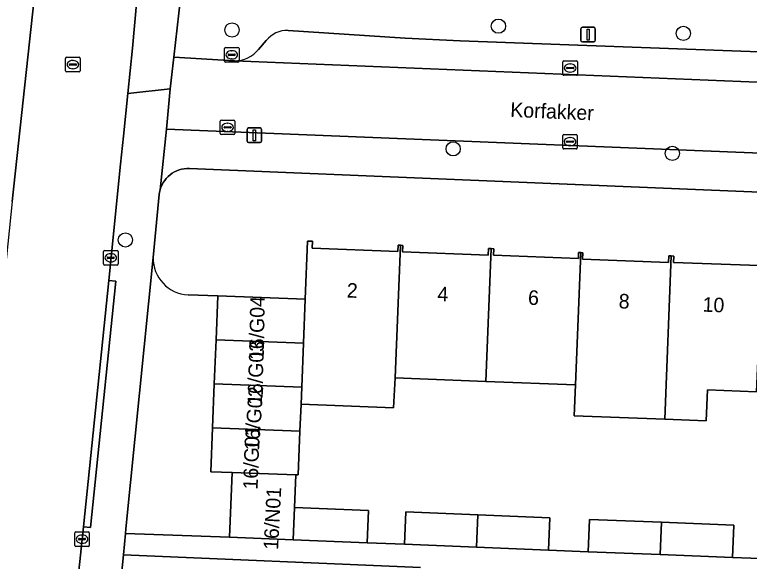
# Model space of a CAD drawing. Extents: x 161354 to 162026, y 386504 to 387460.
# Drawn here: x 161810.3 to 161860.6, y 386901.3 to 386938.8 of the extents above; entities that cross this region are included whole.
import ezdxf

# ---------------------------------------------------------------- set-up
doc = ezdxf.new("R2010")
doc.units = 0
for name, color, linetype in [('IMGEO_Boom', 7, 'Continuous'), ('IMGEO_Erf', 7, 'Continuous'), ('IMGEO_Kolk', 7, 'Continuous'), ('IMGEO_Lichtmast', 7, 'Continuous'), ('IMGEO_Openbare_ruimte_label', 7, 'Continuous'), ('IMGEO_Pand', 7, 'Continuous'), ('IMGEO_Pand_nummerreeks', 7, 'Continuous'), ('IMGEO_Parkeervlak_open', 7, 'Continuous'), ('IMGEO_Rijbaan_lokaal_open', 7, 'Continuous'), ('IMGEO_Rioolput', 7, 'Continuous'), ('IMGEO_Voetpad_gesloten', 7, 'Continuous'), ('IMGEO_Voetpad_open', 7, 'Continuous')]:
    doc.layers.add(name, color=color, linetype=linetype)

msp = doc.modelspace()

# ---------------------------------------------------------------- linework, layer by layer
at = {"layer": 'IMGEO_Boom'}
for centre in [(161843.429, 386938.023), (161825.164, 386937.758), (161856.108, 386937.525), (161840.325, 386929.613), (161855.353, 386929.297), (161817.853, 386923.364)]:
    msp.add_circle(centre, 0.489, dxfattribs=at)
at = {"layer": 'IMGEO_Erf'}
for points in [[(161883.379, 386925.736), (161822.24, 386928.262), (161822.062, 386928.261), (161821.885, 386928.245), (161821.709, 386928.212), (161821.538, 386928.164), (161821.371, 386928.101), (161821.211, 386928.024), (161821.058, 386927.932), (161820.915, 386927.827), (161820.781, 386927.71), (161820.658, 386927.581), (161820.547, 386927.442), (161820.449, 386927.293), (161820.364, 386927.136), (161820.294, 386926.973), (161820.239, 386926.803), (161820.199, 386926.63), (161820.177, 386926.471), (161819.756, 386922.16)], [(161822.159, 386919.611), (161824.182, 386919.533), (161830.18, 386919.302), (161830.335, 386923.288), (161830.673, 386923.275), (161830.655, 386922.794), (161836.533, 386922.568), (161836.549, 386923.007), (161836.715, 386923), (161836.879, 386922.994), (161836.862, 386922.547), (161842.727, 386922.321), (161842.745, 386922.776), (161842.928, 386922.768), (161843.11, 386922.761), (161843.093, 386922.315), (161848.91, 386922.091), (161848.926, 386922.503), (161849.07, 386922.498), (161849.216, 386922.492), (161849.2, 386922.055), (161855.091, 386921.828), (161855.108, 386922.273), (161855.28, 386922.266), (161855.452, 386922.259), (161855.436, 386921.828), (161861.312, 386921.602)], [(161861.132, 386912.953), (161857.774, 386913.082), (161857.682, 386910.965), (161854.828, 386911.075), (161848.617, 386911.314), (161848.703, 386913.432), (161842.56, 386913.668), (161836.347, 386913.907), (161836.227, 386911.855), (161829.9, 386912.098), (161829.821, 386910.252), (161829.694, 386907.265), (161829.54, 386907.27), (161829.449, 386905.022), (161834.521, 386904.817), (161834.432, 386902.599), (161836.982, 386902.496), (161837.071, 386904.714), (161842.017, 386904.515), (161846.963, 386904.316), (161846.873, 386902.097), (161849.583, 386901.988), (161849.673, 386904.206), (161854.619, 386904.007), (161859.56, 386903.808), (161859.47, 386901.589), (161861.984, 386901.488)], [(161838.091, 386900.916), (161817.712, 386901.768), (161815.368, 386878.287)]]:
    msp.add_lwpolyline(points, dxfattribs=at)
msp.add_arc((161822.254, 386922.108), 2.499, 178.8094, 267.813, dxfattribs=at)
at = {"layer": 'IMGEO_Kolk'}
for p, q in [((161824.646, 386935.632), (161824.646, 386936.484)), ((161824.721, 386936.558), (161825.573, 386936.558)), ((161825.134, 386936.338), (161825.159, 386936.338)), ((161825.647, 386936.484), (161825.647, 386935.632)), ((161824.905, 386936.052), (161824.905, 386936.064)), ((161825.343, 386936.015), (161824.945, 386936.015)), ((161824.948, 386936.101), (161825.346, 386936.101)), ((161825.389, 386936.064), (161825.389, 386936.052)), ((161825.573, 386935.558), (161824.721, 386935.558)), ((161825.157, 386935.778), (161825.132, 386935.778)), ((161847.846, 386934.726), (161847.846, 386935.578)), ((161847.921, 386935.652), (161848.773, 386935.652)), ((161848.334, 386935.432), (161848.359, 386935.432)), ((161848.847, 386935.578), (161848.847, 386934.726)), ((161848.105, 386935.146), (161848.105, 386935.158)), ((161848.543, 386935.109), (161848.145, 386935.109)), ((161848.148, 386935.195), (161848.546, 386935.195)), ((161848.357, 386934.872), (161848.332, 386934.872)), ((161848.589, 386935.158), (161848.589, 386935.146)), ((161848.773, 386934.652), (161847.921, 386934.652)), ((161824.356, 386930.66), (161824.356, 386931.512)), ((161824.431, 386931.586), (161825.283, 386931.586)), ((161824.844, 386931.366), (161824.869, 386931.366)), ((161825.357, 386931.512), (161825.357, 386930.66)), ((161824.615, 386931.08), (161824.615, 386931.092)), ((161825.053, 386931.043), (161824.655, 386931.043)), ((161824.658, 386931.129), (161825.056, 386931.129)), ((161824.867, 386930.806), (161824.842, 386930.806)), ((161825.099, 386931.092), (161825.099, 386931.08)), ((161825.283, 386930.586), (161824.431, 386930.586)), ((161847.836, 386929.675), (161847.836, 386930.527)), ((161847.911, 386930.601), (161848.763, 386930.601)), ((161848.324, 386930.381), (161848.349, 386930.381)), ((161848.837, 386930.527), (161848.837, 386929.675)), ((161848.095, 386930.095), (161848.095, 386930.107)), ((161848.533, 386930.058), (161848.135, 386930.058)), ((161848.138, 386930.144), (161848.536, 386930.144)), ((161848.347, 386929.821), (161848.322, 386929.821)), ((161848.579, 386930.107), (161848.579, 386930.095)), ((161848.763, 386929.601), (161847.911, 386929.601)), ((161816.351, 386921.716), (161816.351, 386922.568)), ((161816.426, 386922.642), (161817.278, 386922.642)), ((161816.839, 386922.422), (161816.864, 386922.422)), ((161817.352, 386922.568), (161817.352, 386921.716)), ((161816.61, 386922.136), (161816.61, 386922.148)), ((161817.048, 386922.099), (161816.65, 386922.099)), ((161816.653, 386922.185), (161817.051, 386922.185)), ((161816.862, 386921.862), (161816.837, 386921.862)), ((161817.094, 386922.148), (161817.094, 386922.136)), ((161817.278, 386921.642), (161816.426, 386921.642)), ((161814.379, 386902.423), (161814.379, 386903.275)), ((161814.454, 386903.349), (161815.306, 386903.349)), ((161814.867, 386903.129), (161814.892, 386903.129)), ((161815.38, 386903.275), (161815.38, 386902.423)), ((161814.638, 386902.843), (161814.638, 386902.855)), ((161815.076, 386902.806), (161814.678, 386902.806)), ((161814.681, 386902.892), (161815.079, 386902.892)), ((161815.122, 386902.855), (161815.122, 386902.843)), ((161815.306, 386902.349), (161814.454, 386902.349)), ((161814.89, 386902.569), (161814.865, 386902.569))]:
    msp.add_line(p, q, dxfattribs=at)
for points in [[(161824.646, 386935.632), (161824.646, 386936.484)], [(161824.721, 386936.558), (161825.573, 386936.558)], [(161825.647, 386936.484), (161825.647, 386935.632)], [(161825.573, 386935.558), (161824.721, 386935.558)], [(161847.846, 386934.726), (161847.846, 386935.578)], [(161847.921, 386935.652), (161848.773, 386935.652)], [(161848.847, 386935.578), (161848.847, 386934.726)], [(161848.773, 386934.652), (161847.921, 386934.652)], [(161824.356, 386930.66), (161824.356, 386931.512)], [(161824.431, 386931.586), (161825.283, 386931.586)], [(161825.357, 386931.512), (161825.357, 386930.66)], [(161825.283, 386930.586), (161824.431, 386930.586)], [(161847.836, 386929.675), (161847.836, 386930.527)], [(161847.911, 386930.601), (161848.763, 386930.601)], [(161848.837, 386930.527), (161848.837, 386929.675)], [(161848.763, 386929.601), (161847.911, 386929.601)], [(161816.351, 386921.716), (161816.351, 386922.568)], [(161816.426, 386922.642), (161817.278, 386922.642)], [(161817.352, 386922.568), (161817.352, 386921.716)], [(161817.278, 386921.642), (161816.426, 386921.642)], [(161814.379, 386902.423), (161814.379, 386903.275)], [(161814.454, 386903.349), (161815.306, 386903.349)], [(161815.38, 386903.275), (161815.38, 386902.423)], [(161815.306, 386902.349), (161814.454, 386902.349)]]:
    msp.add_lwpolyline(points, dxfattribs=at)
for centre, radius, start, end in [((161824.723, 386936.482), 0.0765, 91.552, 178.448), ((161824.723, 386936.482), 0.0765, 91.552, 178.448), ((161825.571, 386936.482), 0.0765, 1.552, 88.448), ((161825.571, 386936.482), 0.0765, 1.552, 88.448), ((161824.945, 386936.061), 0.0403, 85.8775, 175.7526), ((161824.942, 386936.051), 0.0366, 178.938, 274.7102), ((161825.346, 386936.058), 0.043, 264.8664, 352.4533), ((161825.35, 386936.063), 0.0386, 1.7309, 96.639), ((161824.723, 386935.634), 0.0765, 181.552, 268.448), ((161824.723, 386935.634), 0.0765, 181.552, 268.448), ((161825.571, 386935.634), 0.0765, 271.552, 358.448), ((161825.571, 386935.634), 0.0765, 271.552, 358.448), ((161847.923, 386935.576), 0.0765, 91.552, 178.448), ((161847.923, 386935.576), 0.0765, 91.552, 178.448), ((161848.771, 386935.576), 0.0765, 1.552, 88.448), ((161848.771, 386935.576), 0.0765, 1.552, 88.448), ((161848.145, 386935.155), 0.0403, 85.8775, 175.7526), ((161848.142, 386935.145), 0.0366, 178.938, 274.7102), ((161848.546, 386935.152), 0.043, 264.8664, 352.4533), ((161848.55, 386935.157), 0.0386, 1.7309, 96.639), ((161847.923, 386934.728), 0.0765, 181.552, 268.448), ((161847.923, 386934.728), 0.0765, 181.552, 268.448), ((161848.771, 386934.728), 0.0765, 271.552, 358.448), ((161848.771, 386934.728), 0.0765, 271.552, 358.448), ((161824.433, 386931.51), 0.0765, 91.552, 178.448), ((161824.433, 386931.51), 0.0765, 91.552, 178.448), ((161825.281, 386931.51), 0.0765, 1.552, 88.448), ((161825.281, 386931.51), 0.0765, 1.552, 88.448), ((161824.655, 386931.089), 0.0403, 85.8775, 175.7526), ((161824.652, 386931.079), 0.0366, 178.938, 274.7102), ((161825.056, 386931.086), 0.043, 264.8664, 352.4533), ((161825.06, 386931.091), 0.0386, 1.7309, 96.639), ((161824.433, 386930.662), 0.0765, 181.552, 268.448), ((161824.433, 386930.662), 0.0765, 181.552, 268.448), ((161825.281, 386930.662), 0.0765, 271.552, 358.448), ((161825.281, 386930.662), 0.0765, 271.552, 358.448), ((161847.913, 386930.525), 0.0765, 91.552, 178.448), ((161847.913, 386930.525), 0.0765, 91.552, 178.448), ((161848.761, 386930.525), 0.0765, 1.552, 88.448), ((161848.761, 386930.525), 0.0765, 1.552, 88.448), ((161848.135, 386930.104), 0.0403, 85.8775, 175.7526), ((161848.132, 386930.094), 0.0366, 178.938, 274.7102), ((161848.536, 386930.101), 0.043, 264.8664, 352.4533), ((161848.54, 386930.106), 0.0386, 1.7309, 96.639), ((161847.913, 386929.677), 0.0765, 181.552, 268.448), ((161847.913, 386929.677), 0.0765, 181.552, 268.448), ((161848.761, 386929.677), 0.0765, 271.552, 358.448), ((161848.761, 386929.677), 0.0765, 271.552, 358.448), ((161816.428, 386922.566), 0.0765, 91.552, 178.448), ((161816.428, 386922.566), 0.0765, 91.552, 178.448), ((161817.276, 386922.566), 0.0765, 1.552, 88.448), ((161817.276, 386922.566), 0.0765, 1.552, 88.448), ((161816.65, 386922.145), 0.0403, 85.8775, 175.7526), ((161816.647, 386922.135), 0.0366, 178.938, 274.7102), ((161817.051, 386922.142), 0.043, 264.8664, 352.4533), ((161817.055, 386922.147), 0.0386, 1.7309, 96.639), ((161816.428, 386921.718), 0.0765, 181.552, 268.448), ((161816.428, 386921.718), 0.0765, 181.552, 268.448), ((161817.276, 386921.718), 0.0765, 271.552, 358.448), ((161817.276, 386921.718), 0.0765, 271.552, 358.448), ((161814.456, 386903.273), 0.0765, 91.552, 178.448), ((161814.456, 386903.273), 0.0765, 91.552, 178.448), ((161815.304, 386903.273), 0.0765, 1.552, 88.448), ((161815.304, 386903.273), 0.0765, 1.552, 88.448), ((161814.678, 386902.852), 0.0403, 85.8775, 175.7526), ((161814.675, 386902.842), 0.0366, 178.938, 274.7102), ((161815.079, 386902.849), 0.043, 264.8664, 352.4533), ((161815.083, 386902.854), 0.0386, 1.7309, 96.639), ((161814.456, 386902.425), 0.0765, 181.552, 268.448), ((161814.456, 386902.425), 0.0765, 181.552, 268.448), ((161815.304, 386902.425), 0.0765, 271.552, 358.448), ((161815.304, 386902.425), 0.0765, 271.552, 358.448)]:
    msp.add_arc(centre, radius, start, end, dxfattribs=at)
for centre, major_axis, ratio, start_param, end_param in [((161825.133, 386936.058), (-0.387, 0.002), 0.722429, 4.712389, 7.853982), ((161825.158, 386936.058), (-0.39, 0.002), 0.717154, 1.570796, 4.712389), ((161848.333, 386935.152), (-0.387, 0.002), 0.722429, 4.712389, 7.853982), ((161848.358, 386935.152), (-0.39, 0.002), 0.717154, 1.570796, 4.712389), ((161824.843, 386931.086), (-0.387, 0.002), 0.722429, 4.712389, 7.853982), ((161824.868, 386931.086), (-0.39, 0.002), 0.717154, 1.570796, 4.712389), ((161848.323, 386930.101), (-0.387, 0.002), 0.722429, 4.712389, 7.853982), ((161848.348, 386930.101), (-0.39, 0.002), 0.717154, 1.570796, 4.712389), ((161816.838, 386922.142), (-0.387, 0.002), 0.722429, 4.712389, 7.853982), ((161816.863, 386922.142), (-0.39, 0.002), 0.717154, 1.570796, 4.712389), ((161814.866, 386902.849), (-0.387, 0.002), 0.722429, 4.712389, 7.853982), ((161814.891, 386902.849), (-0.39, 0.002), 0.717154, 1.570796, 4.712389)]:
    msp.add_ellipse(centre, major_axis=major_axis, ratio=ratio, start_param=start_param, end_param=end_param, dxfattribs=at)
at = {"layer": 'IMGEO_Lichtmast'}
for p, q in [((161849.082, 386937.047), (161849.082, 386937.847)), ((161849.082, 386937.847), (161849.082, 386937.047)), ((161849.182, 386937.947), (161849.972, 386937.947)), ((161849.972, 386937.947), (161849.182, 386937.947)), ((161850.072, 386937.847), (161850.072, 386937.047)), ((161850.072, 386937.047), (161850.072, 386937.847)), ((161849.972, 386936.947), (161849.182, 386936.947)), ((161849.182, 386936.947), (161849.972, 386936.947)), ((161826.2, 386930.142), (161826.2, 386930.942)), ((161826.2, 386930.942), (161826.2, 386930.142)), ((161826.3, 386931.042), (161827.09, 386931.042)), ((161827.09, 386931.042), (161826.3, 386931.042)), ((161827.19, 386930.942), (161827.19, 386930.142)), ((161827.19, 386930.142), (161827.19, 386930.942)), ((161827.09, 386930.042), (161826.3, 386930.042)), ((161826.3, 386930.042), (161827.09, 386930.042))]:
    msp.add_line(p, q, dxfattribs=at)
for points in [[(161849.502, 386937.822), (161849.652, 386937.822), (161849.652, 386937.072), (161849.502, 386937.072), (161849.502, 386937.822)], [(161826.62, 386930.917), (161826.77, 386930.917), (161826.77, 386930.167), (161826.62, 386930.167), (161826.62, 386930.917)]]:
    msp.add_lwpolyline(points, dxfattribs=at)
for centre, start, end in [((161849.182, 386937.847), 90, 180), ((161849.182, 386937.847), 90, 180), ((161849.972, 386937.847), 0, 90), ((161849.972, 386937.847), 360, 90), ((161849.182, 386937.047), 180, 270), ((161849.182, 386937.047), 180, 270), ((161849.972, 386937.047), 270, 0), ((161849.972, 386937.047), 270, 0), ((161826.3, 386930.942), 90, 180), ((161826.3, 386930.942), 90, 180), ((161827.09, 386930.942), 0, 90), ((161827.09, 386930.942), 360, 90), ((161826.3, 386930.142), 180, 270), ((161826.3, 386930.142), 180, 270), ((161827.09, 386930.142), 270, 0), ((161827.09, 386930.142), 270, 0)]:
    msp.add_arc(centre, 0.1, start, end, dxfattribs=at)
at = {"layer": 'IMGEO_Pand'}
for points in [[(161836.227, 386911.855), (161836.347, 386913.907), (161836.715, 386923), (161836.549, 386923.007), (161836.533, 386922.568), (161830.655, 386922.794), (161830.673, 386923.275), (161830.335, 386923.288), (161830.18, 386919.302), (161830.063, 386916.285), (161829.945, 386913.268), (161829.9, 386912.098)], [(161842.56, 386913.668), (161842.928, 386922.768), (161842.745, 386922.776), (161842.727, 386922.321), (161836.862, 386922.547), (161836.879, 386922.994), (161836.715, 386923), (161836.347, 386913.907)], [(161848.703, 386913.432), (161849.07, 386922.498), (161848.926, 386922.503), (161848.91, 386922.091), (161843.093, 386922.315), (161843.11, 386922.761), (161842.928, 386922.768), (161842.56, 386913.668)], [(161848.617, 386911.314), (161854.828, 386911.075), (161855.28, 386922.266), (161855.108, 386922.273), (161855.091, 386921.828), (161849.2, 386922.055), (161849.216, 386922.492), (161849.07, 386922.498), (161848.703, 386913.432)], [(161857.682, 386910.965), (161857.774, 386913.082), (161861.132, 386912.953), (161861.5, 386922.048), (161861.329, 386922.055), (161861.312, 386921.602), (161855.436, 386921.828), (161855.452, 386922.259), (161855.28, 386922.266), (161854.828, 386911.075)], [(161824.066, 386916.516), (161830.063, 386916.285), (161830.18, 386919.302), (161824.182, 386919.533)], [(161824.066, 386916.516), (161823.95, 386913.499), (161829.945, 386913.268), (161830.063, 386916.285)], [(161823.95, 386913.499), (161823.834, 386910.482), (161829.821, 386910.252), (161829.9, 386912.098), (161829.945, 386913.268)], [(161829.821, 386910.252), (161823.834, 386910.482), (161823.718, 386907.465), (161825.17, 386907.416), (161829.54, 386907.27), (161829.694, 386907.265)], [(161829.54, 386907.27), (161825.17, 386907.416), (161824.991, 386902.98), (161829.36, 386902.803), (161829.449, 386905.022)], [(161829.449, 386905.022), (161829.36, 386902.803), (161834.432, 386902.599), (161834.521, 386904.817)], [(161842.017, 386904.515), (161837.071, 386904.714), (161836.982, 386902.496), (161841.928, 386902.297)], [(161842.017, 386904.515), (161841.928, 386902.297), (161846.873, 386902.097), (161846.963, 386904.316)], [(161854.619, 386904.007), (161849.673, 386904.206), (161849.583, 386901.988), (161854.529, 386901.789)], [(161854.619, 386904.007), (161854.529, 386901.789), (161859.47, 386901.589), (161859.56, 386903.808)]]:
    msp.add_lwpolyline(points, close=True, dxfattribs=at)
at = {"layer": 'IMGEO_Parkeervlak_open'}
for points in [[(161840.813, 386937.012), (161837.043, 386937.189), (161829.008, 386937.73)], [(161827.515, 386937.033), (161826.99, 386936.43)], [(161865.649, 386936.106), (161840.813, 386937.012)], [(161825.331, 386935.656), (161869.016, 386933.873)]]:
    msp.add_lwpolyline(points, dxfattribs=at)
for centre, radius, start, end in [((161828.94, 386935.929), 1.802, 87.8264, 142.2242), ((161825.369, 386937.739), 2.083, 268.9502, 321.0723)]:
    msp.add_arc(centre, radius, start, end, dxfattribs=at)
at = {"layer": 'IMGEO_Rijbaan_lokaal_open'}
msp.add_lwpolyline([(161816.71, 386920.59), (161817.528, 386928.566), (161817.724, 386930.482), (161818.023, 386933.401), (161818.343, 386936.515), (161819.44, 386948.763), (161812.576, 386949.497), (161812.049, 386944.655), (161812.024, 386943.912), (161810.085, 386925.992), (161809.785, 386923.091), (161808.152, 386907.304), (161805.29, 386878.733), (161812.271, 386878.019), (161814.977, 386903.685)], close=True, dxfattribs=at)
for points in [[(161810.085, 386925.992), (161812.024, 386943.912), (161812.049, 386944.655)], [(161872.055, 386933.83), (161869.016, 386933.873), (161825.331, 386935.656), (161821.164, 386935.889), (161820.927, 386933.732), (161820.663, 386930.949), (161873.861, 386928.802)]]:
    msp.add_lwpolyline(points, dxfattribs=at)
at = {"layer": 'IMGEO_Rioolput'}
for p, q in [((161813.826, 386935.887), (161814.678, 386935.887)), ((161813.751, 386934.961), (161813.751, 386935.813)), ((161814.01, 386935.381), (161814.01, 386935.393)), ((161814.448, 386935.344), (161814.05, 386935.344)), ((161814.053, 386935.43), (161814.451, 386935.43)), ((161814.239, 386935.667), (161814.264, 386935.667)), ((161814.494, 386935.393), (161814.494, 386935.381)), ((161814.752, 386935.813), (161814.752, 386934.961)), ((161814.678, 386934.887), (161813.826, 386934.887)), ((161814.262, 386935.107), (161814.237, 386935.107))]:
    msp.add_line(p, q, dxfattribs=at)
for points in [[(161813.826, 386935.887), (161814.678, 386935.887)], [(161813.751, 386934.961), (161813.751, 386935.813)], [(161814.752, 386935.813), (161814.752, 386934.961)], [(161814.678, 386934.887), (161813.826, 386934.887)]]:
    msp.add_lwpolyline(points, dxfattribs=at)
for centre, radius, start, end in [((161813.828, 386935.811), 0.0765, 91.552, 178.448), ((161813.828, 386935.811), 0.0765, 91.552, 178.448), ((161814.676, 386935.811), 0.0765, 1.552, 88.448), ((161814.676, 386935.811), 0.0765, 1.552, 88.448), ((161814.05, 386935.39), 0.0403, 85.8775, 175.7526), ((161814.047, 386935.38), 0.0366, 178.938, 274.7102), ((161814.451, 386935.387), 0.043, 264.8664, 352.4533), ((161814.455, 386935.392), 0.0386, 1.7309, 96.639), ((161813.828, 386934.963), 0.0765, 181.552, 268.448), ((161813.828, 386934.963), 0.0765, 181.552, 268.448), ((161814.676, 386934.963), 0.0765, 271.552, 358.448), ((161814.676, 386934.963), 0.0765, 271.552, 358.448)]:
    msp.add_arc(centre, radius, start, end, dxfattribs=at)
for centre, major_axis, ratio, start_param, end_param in [((161814.238, 386935.387), (-0.387, 0.002), 0.722429, 4.712389, 7.853982), ((161814.263, 386935.387), (-0.39, 0.002), 0.717154, 1.570796, 4.712389)]:
    msp.add_ellipse(centre, major_axis=major_axis, ratio=ratio, start_param=start_param, end_param=end_param, dxfattribs=at)
at = {"layer": 'IMGEO_Voetpad_gesloten'}
msp.add_lwpolyline([(161861.984, 386901.488), (161859.47, 386901.589), (161854.529, 386901.789), (161849.583, 386901.988), (161846.873, 386902.097), (161841.928, 386902.297), (161836.982, 386902.496), (161834.432, 386902.599), (161829.36, 386902.803), (161824.991, 386902.98), (161817.859, 386903.237), (161817.712, 386901.768), (161838.091, 386900.916)], dxfattribs=at)
at = {"layer": 'IMGEO_Voetpad_open'}
for points in [[(161819.44, 386948.763), (161818.343, 386936.515), (161818.023, 386933.401), (161820.927, 386933.732), (161821.164, 386935.889), (161821.982, 386942.958)], [(161821.982, 386942.958), (161821.164, 386935.889), (161825.331, 386935.656)], [(161829.008, 386937.73), (161837.043, 386937.189), (161840.813, 386937.012), (161865.649, 386936.106), (161865.891, 386938.984)], [(161826.99, 386936.43), (161827.515, 386937.033)], [(161815.368, 386878.287), (161817.712, 386901.768), (161817.859, 386903.237), (161817.89, 386903.552), (161819.756, 386922.16), (161820.177, 386926.471), (161820.199, 386926.63), (161820.239, 386926.803), (161820.663, 386930.949), (161820.927, 386933.732), (161818.023, 386933.401), (161817.724, 386930.482), (161817.528, 386928.566), (161816.71, 386920.59), (161817.189, 386920.547), (161815.461, 386903.641), (161814.977, 386903.685), (161812.271, 386878.019), (161812.005, 386875.25), (161811.96, 386874.964)], [(161873.861, 386928.802), (161820.663, 386930.949), (161820.239, 386926.803), (161820.294, 386926.973), (161820.364, 386927.136), (161820.449, 386927.293), (161820.547, 386927.442), (161820.658, 386927.581), (161820.781, 386927.71), (161820.915, 386927.827), (161821.058, 386927.932), (161821.211, 386928.024), (161821.371, 386928.101), (161821.538, 386928.164), (161821.709, 386928.212), (161821.885, 386928.245), (161822.062, 386928.261), (161822.24, 386928.262), (161883.379, 386925.736), (161886.318, 386925.615), (161886.54, 386930.68)], [(161819.756, 386922.16), (161817.89, 386903.552), (161817.859, 386903.237), (161824.991, 386902.98), (161825.17, 386907.416), (161823.718, 386907.465), (161823.834, 386910.482), (161823.95, 386913.499)], [(161823.95, 386913.499), (161824.066, 386916.516), (161824.182, 386919.533), (161822.159, 386919.611)]]:
    msp.add_lwpolyline(points, dxfattribs=at)
msp.add_lwpolyline([(161814.977, 386903.685), (161815.461, 386903.641), (161817.189, 386920.547), (161816.71, 386920.59)], close=True, dxfattribs=at)
for centre, radius, start, end in [((161828.94, 386935.929), 1.802, 87.8264, 142.2242), ((161825.369, 386937.739), 2.083, 268.9502, 321.0723), ((161822.254, 386922.108), 2.499, 178.8094, 267.813)]:
    msp.add_arc(centre, radius, start, end, dxfattribs=at)

# ---------------------------------------------------------------- texts
at = {"layer": 'IMGEO_Openbare_ruimte_label'}
msp.add_text('Korfakker', height=1, rotation=357.5926, dxfattribs=at).set_placement((161844.225, 386931.805))
at = {"layer": 'IMGEO_Pand_nummerreeks'}
for s, rotation, p in [('2', 357.7291, (161833.016, 386919.417)), ('4', 357.7291, (161839.231, 386919.171)), ('6', 357.7291, (161845.443, 386918.924)), ('16/G04', 89.029, (161827.338, 386915.122)), ('8', 357.7291, (161851.66, 386918.678)), ('10', 357.7291, (161857.412, 386918.45)), ('16/G03', 88.0585, (161827.214, 386912.039)), ('16/G02', 86.1215, (161827.012, 386908.899)), ('16/G01', 87.9891, (161826.916, 386906.238)), ('16/N01', 87.0036, (161828.319, 386902.096))]:
    msp.add_text(s, height=1, rotation=rotation, dxfattribs=at).set_placement(p)

doc.saveas('drawing.dxf')
